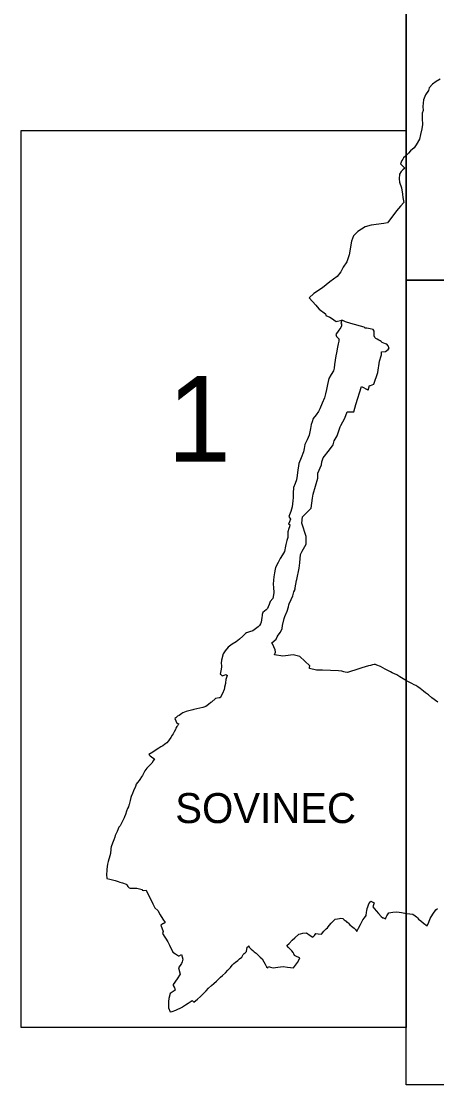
# Model space of a CAD drawing. Extents: x -547343 to -529607, y -1096298 to -1087453.
# Drawn here: x -535595.4 to -535501.3, y -1089568.3 to -1089327.3 of the extents above; entities that cross this region are included whole.
import ezdxf

# ---------------------------------------------------------------- set-up
doc = ezdxf.new("R2010")
doc.units = 0
doc.layers.add('Vrstva 18', color=7, linetype='Continuous')
doc.layers.add('Vrstva 9', color=7, linetype='Continuous')

msp = doc.modelspace()

# ---------------------------------------------------------------- linework, layer by layer
at = {"layer": 'Vrstva 18'}
for points in [[(-535421.05, -1089203.69), (-535508.22, -1089203.69), (-535508.22, -1089386.02), (-535421.05, -1089386.02)], [(-535508.22, -1089352.1), (-535508.22, -1089555.37), (-535595.39, -1089555.37), (-535595.39, -1089352.1)], [(-535421.05, -1089386.02), (-535421.05, -1089568.34), (-535508.22, -1089568.34), (-535508.22, -1089386.02)]]:
    msp.add_lwpolyline(points, close=True, dxfattribs=at)
for points in [[(-535500.53, -1089340.43), (-535501.42, -1089340.96), (-535502.32, -1089341.55), (-535503.04, -1089342.41), (-535503.2, -1089343.02), (-535503.9, -1089344.01), (-535504.36, -1089345.11), (-535504.45, -1089346.64), (-535504.37, -1089347.55), (-535504.59, -1089348.18), (-535504.66, -1089349.38), (-535504.57, -1089350.69), (-535504.67, -1089351.72), (-535504.99, -1089352.99), (-535505.24, -1089354.03), (-535505.98, -1089355.32), (-535506.47, -1089356), (-535507.27, -1089356.66), (-535507.75, -1089357.22), (-535508.42, -1089357.88), (-535508.82, -1089358.3), (-535508.98, -1089358.61), (-535509.25, -1089358.88), (-535509.51, -1089359.62), (-535509.17, -1089360.03), (-535508.53, -1089360.59), (-535508.97, -1089361.01), (-535509.37, -1089361.39), (-535509.77, -1089361.95), (-535509.84, -1089363.02), (-535509.77, -1089363.78), (-535509.33, -1089365.09), (-535509.09, -1089366.52), (-535509, -1089367.28), (-535508.78, -1089368.41), (-535509.53, -1089369.24), (-535510.45, -1089370.32), (-535511.07, -1089371.09), (-535512.27, -1089372.72), (-535512.45, -1089373), (-535513.34, -1089373.2), (-535516.16, -1089373.56), (-535517.56, -1089373.9), (-535519.23, -1089374.98), (-535520.16, -1089375.96), (-535520.62, -1089377.17), (-535521.15, -1089380.26), (-535521.65, -1089381.83), (-535522.55, -1089383.08), (-535523.01, -1089384.11), (-535523.86, -1089385.16), (-535525.57, -1089386.4), (-535527.22, -1089387.73), (-535529.16, -1089389.06), (-535530.23, -1089390.03), (-535528.72, -1089391.66), (-535528.41, -1089392.07), (-535527.96, -1089392.55), (-535526.54, -1089393.64), (-535526.43, -1089393.98), (-535525.53, -1089394.36), (-535524.94, -1089394.75), (-535524.6, -1089395), (-535524.1, -1089395.35), (-535522.78, -1089395.07), (-535523.03, -1089395.8), (-535522.86, -1089395.83), (-535522.89, -1089396.32), (-535523.08, -1089396.74), (-535523.48, -1089397.33), (-535524.17, -1089398.31), (-535523.99, -1089398.8), (-535523.45, -1089399.38), (-535523.49, -1089399.56), (-535523.53, -1089399.8), (-535523.66, -1089400.43), (-535523.79, -1089401.2), (-535524.02, -1089402.47), (-535524.15, -1089403.19), (-535524.32, -1089404.12), (-535524.46, -1089405.1), (-535524.58, -1089405.96), (-535524.67, -1089406.56), (-535525.21, -1089407.42), (-535525.73, -1089408.28), (-535526.05, -1089409.68), (-535526.3, -1089410.8), (-535526.54, -1089411.74), (-535526.77, -1089412.64), (-535527.29, -1089413.91), (-535527.8, -1089415.14), (-535528.07, -1089415.78), (-535528.63, -1089416.49), (-535529.34, -1089417.37), (-535529.55, -1089418.09), (-535529.74, -1089418.7), (-535529.9, -1089419.6), (-535530.06, -1089420.4), (-535530.18, -1089421.1), (-535530.66, -1089422.16), (-535531.17, -1089423.27), (-535531.32, -1089424.12), (-535531.48, -1089424.88), (-535532.02, -1089426.26), (-535532.55, -1089427.55), (-535532.82, -1089429.6), (-535532.93, -1089430.3), (-535533.06, -1089431.28), (-535533.39, -1089432.07), (-535533.78, -1089432.98), (-535533.84, -1089434.3), (-535533.86, -1089435.23), (-535533.9, -1089435.98), (-535533.96, -1089436.68), (-535534.03, -1089437.37), (-535534.4, -1089438.45), (-535534.78, -1089439.53), (-535534.45, -1089440.16), (-535534.69, -1089440.78), (-535534.91, -1089441.32), (-535534.61, -1089441.36), (-535534.64, -1089441.89), (-535534.78, -1089442.29), (-535535.03, -1089443.07), (-535535.05, -1089443.59), (-535535.08, -1089444.3), (-535535.25, -1089444.97), (-535535.5, -1089445.89), (-535535.58, -1089446.27), (-535535.81, -1089447.51), (-535536.28, -1089448.26), (-535536.8, -1089449.09), (-535537.25, -1089450), (-535537.8, -1089451.15), (-535537.88, -1089451.49), (-535538.08, -1089452.32), (-535538.24, -1089453.24), (-535538.3, -1089453.99), (-535538.36, -1089454.9), (-535538.3, -1089455.65), (-535538.22, -1089456.79), (-535538.3, -1089457.33), (-535538.41, -1089458.12), (-535539.05, -1089458.84), (-535539.27, -1089459.53), (-535539.47, -1089460.07), (-535539.61, -1089460.39), (-535539.96, -1089460.7), (-535540.7, -1089461.3), (-535540.85, -1089461.76), (-535540.86, -1089461.97), (-535540.9, -1089462.45), (-535541.06, -1089463.49), (-535541.25, -1089463.88), (-535541.49, -1089464.23), (-535541.78, -1089464.59), (-535542.33, -1089465.02), (-535542.97, -1089465.51), (-535543.69, -1089465.67), (-535544.37, -1089465.93), (-535544.59, -1089466.06), (-535545.25, -1089466.66), (-535546.01, -1089467.39), (-535546.76, -1089467.94), (-535547.62, -1089468.51), (-535548.57, -1089469.16), (-535549.22, -1089469.98), (-535549.55, -1089470.44), (-535549.68, -1089470.71), (-535550.04, -1089472.13), (-535550.1, -1089472.79), (-535550.03, -1089473.41), (-535550.08, -1089473.74), (-535550.24, -1089474.53), (-535550.34, -1089475.3), (-535550.24, -1089475.37), (-535549.95, -1089475.58), (-535549.95, -1089475.58), (-535549.93, -1089475.59), (-535549.85, -1089475.65), (-535549.06, -1089475.38), (-535548.98, -1089475.43), (-535548.86, -1089475.51), (-535548.79, -1089475.55), (-535548.77, -1089475.57), (-535549.09, -1089476.47), (-535549.15, -1089477.22), (-535549.17, -1089477.42), (-535549.35, -1089478.21), (-535549.38, -1089478.36), (-535549.48, -1089478.78), (-535549.8, -1089479.66), (-535550.4, -1089480.68), (-535550.5, -1089480.64), (-535550.62, -1089480.62), (-535551.42, -1089480.79), (-535552.35, -1089481.61), (-535552.46, -1089481.7), (-535553.04, -1089482.18), (-535553.61, -1089482.59), (-535554.31, -1089482.86), (-535556.33, -1089483.31), (-535556.55, -1089483.36), (-535556.83, -1089483.43), (-535558.09, -1089483.74), (-535558.46, -1089483.9), (-535558.82, -1089484.06), (-535559.08, -1089484.24), (-535559.67, -1089484.64), (-535559.99, -1089484.84), (-535560.39, -1089485.18), (-535560.62, -1089485.37), (-535560.42, -1089485.87), (-535560.15, -1089486.41), (-535559.75, -1089486.55), (-535559.85, -1089486.72), (-535560.03, -1089486.99), (-535560.15, -1089487.18), (-535560.39, -1089487.55), (-535560.51, -1089487.81), (-535560.79, -1089488.36), (-535560.99, -1089488.78), (-535561.22, -1089489.12), (-535561.54, -1089489.62), (-535561.9, -1089490.19), (-535562.07, -1089490.38), (-535562.46, -1089490.84), (-535562.65, -1089491.03), (-535562.97, -1089491.25), (-535563.38, -1089491.53), (-535563.77, -1089491.77), (-535564.24, -1089492.09), (-535564.83, -1089492.47), (-535565.62, -1089492.97), (-535566.5, -1089493.51), (-535566.42, -1089493.59), (-535566.21, -1089493.78), (-535565.64, -1089494.25), (-535565.21, -1089494.46), (-535565.5, -1089494.91), (-535565.85, -1089495.45), (-535566.21, -1089495.82), (-535566.62, -1089496.23), (-535566.98, -1089496.59), (-535567.18, -1089496.89), (-535567.41, -1089497.2), (-535567.66, -1089497.69), (-535567.95, -1089498.22), (-535568.17, -1089498.59), (-535568.57, -1089499.2), (-535568.69, -1089499.36), (-535569.1, -1089499.87), (-535569.35, -1089500.2), (-535569.57, -1089500.78), (-535569.95, -1089501.73), (-535570.2, -1089502.31), (-535570.5, -1089503), (-535570.57, -1089503.27), (-535570.73, -1089503.94), (-535570.96, -1089504.84), (-535571.02, -1089504.99), (-535571.15, -1089505.33), (-535571.33, -1089505.74), (-535571.55, -1089506.33), (-535571.81, -1089507.1), (-535572.01, -1089507.66), (-535572.11, -1089507.88), (-535572.7, -1089509.03), (-535573.04, -1089509.65), (-535573.27, -1089509.98), (-535573.44, -1089510.38), (-535573.72, -1089510.98), (-535574.13, -1089511.89), (-535574.24, -1089512.21), (-535574.46, -1089512.82), (-535574.75, -1089513.6), (-535575.05, -1089514.4), (-535575.11, -1089514.8), (-535575.13, -1089515.08), (-535575.19, -1089515.75), (-535575.23, -1089515.96), (-535575.37, -1089516.5), (-535575.71, -1089517.73), (-535575.88, -1089518.35), (-535575.92, -1089518.89), (-535575.99, -1089519.55), (-535576.02, -1089519.82), (-535576.1, -1089520.72), (-535576.01, -1089521.62), (-535575.38, -1089521.74), (-535574.71, -1089521.89), (-535574.16, -1089522.08), (-535573.45, -1089522.3), (-535573.05, -1089522.43), (-535572.46, -1089522.61), (-535571.62, -1089522.86), (-535571.46, -1089523.07), (-535571.24, -1089523.38), (-535570.99, -1089523.73), (-535570.77, -1089523.76), (-535570.19, -1089523.82), (-535569.24, -1089523.81), (-535568.29, -1089524.01), (-535568.06, -1089524.12), (-535568, -1089524.26), (-535567.79, -1089524.33), (-535567.1, -1089524.23), (-535565.63, -1089527.36), (-535565.12, -1089528.22), (-535564.44, -1089528.83), (-535563.95, -1089529.81), (-535563.37, -1089530.85), (-535562.78, -1089531.54), (-535563.15, -1089531.76), (-535563.32, -1089531.87), (-535563.78, -1089532.15), (-535563.25, -1089533.63), (-535563.39, -1089534.1), (-535562.18, -1089535.95), (-535561.85, -1089536.69), (-535561.09, -1089538.31), (-535560.48, -1089538.67), (-535559.81, -1089539.13), (-535559.63, -1089539.09), (-535559.09, -1089538.82), (-535558.84, -1089539.87), (-535558.95, -1089540.51), (-535559.09, -1089540.9), (-535559.78, -1089541.88), (-535559.43, -1089543.26), (-535560.08, -1089544.3), (-535561.04, -1089545.59), (-535561.02, -1089545.86), (-535560.78, -1089546.19), (-535560.7, -1089546.32), (-535560.63, -1089546.65), (-535560.58, -1089546.89), (-535561.68, -1089547.65), (-535561.97, -1089548.81), (-535562.06, -1089549.49), (-535562.09, -1089549.73), (-535562.09, -1089550.93), (-535561.69, -1089551.79), (-535561.22, -1089551.76), (-535560.37, -1089551.45), (-535559, -1089550.76), (-535558.87, -1089550.68), (-535558.18, -1089550.26), (-535557.61, -1089549.88), (-535556.68, -1089549.25), (-535556.47, -1089549.49), (-535556.33, -1089549.65), (-535555.47, -1089548.98), (-535554.81, -1089548.31), (-535554.31, -1089547.81), (-535553.56, -1089547.04), (-535552.99, -1089546.48), (-535552.32, -1089545.82), (-535551.83, -1089545.4), (-535551.22, -1089544.86), (-535550.79, -1089544.48), (-535550.26, -1089543.98), (-535549.81, -1089543.55), (-535549.19, -1089542.94), (-535548.64, -1089542.41), (-535548.01, -1089541.77), (-535547.61, -1089541.26), (-535547.28, -1089540.83), (-535546.87, -1089540.54), (-535546.38, -1089540.18), (-535545.97, -1089539.83), (-535545.48, -1089539.4), (-535545.3, -1089539.13), (-535545.12, -1089538.8), (-535544.92, -1089538.63), (-535544.74, -1089538.45), (-535544.43, -1089538.14), (-535544.26, -1089537.19), (-535544.05, -1089537.02), (-535543.87, -1089536.87), (-535543.82, -1089537.18), (-535543.48, -1089537.48), (-535543.33, -1089537.62), (-535542.98, -1089537.93), (-535542.64, -1089538.22), (-535542.24, -1089538.55), (-535541.91, -1089538.83), (-535541.62, -1089539.09), (-535541.28, -1089539.39), (-535540.82, -1089539.82), (-535540.48, -1089540.45), (-535540.19, -1089540.98), (-535539.86, -1089541.65), (-535539.56, -1089541.82), (-535539.41, -1089541.52), (-535538.93, -1089541.68), (-535538.37, -1089541.87), (-535537.31, -1089541.72), (-535536.12, -1089541.56), (-535535.12, -1089541.66), (-535533.73, -1089541.81), (-535533.33, -1089541.27), (-535532.84, -1089540.62), (-535532.56, -1089540.07), (-535532.35, -1089539.61), (-535532.9, -1089539.36), (-535533.56, -1089539.05), (-535533.69, -1089538.68), (-535533.81, -1089538.34), (-535534.14, -1089538.02), (-535534.88, -1089537.24), (-535535.3, -1089536.82), (-535534.77, -1089536.32), (-535534.03, -1089535.6), (-535533.45, -1089535.05), (-535532.54, -1089534.19), (-535532.19, -1089534.11), (-535531.63, -1089534.01), (-535530.85, -1089533.89), (-535529.98, -1089534.48), (-535529.37, -1089534.9), (-535529.04, -1089534.5), (-535528.67, -1089534.08), (-535528.15, -1089534.13), (-535527.42, -1089534.19), (-535526.86, -1089533.54), (-535526.38, -1089533), (-535526.08, -1089532.76), (-535525.67, -1089532.24), (-535525.24, -1089531.7), (-535524.8, -1089531.26), (-535524.33, -1089530.82), (-535523.8, -1089530.72), (-535523.38, -1089530.65), (-535523.07, -1089530.62), (-535522.6, -1089530.67), (-535522.26, -1089530.96), (-535521.87, -1089531.3), (-535521.68, -1089531.48), (-535521.57, -1089531.56), (-535521.4, -1089531.64), (-535521.02, -1089532.1), (-535520.61, -1089532.41), (-535520.04, -1089532.82), (-535519.75, -1089533.18), (-535519.4, -1089533.59), (-535519.03, -1089532.88), (-535518.61, -1089532.04), (-535518.35, -1089531.55), (-535518.04, -1089530.95), (-535517.69, -1089530.48), (-535517.34, -1089530), (-535517.2, -1089529.23), (-535517.14, -1089528.89), (-535517.05, -1089528.43), (-535516.93, -1089528.01), (-535516.73, -1089527.34), (-535516.28, -1089526.74), (-535515.47, -1089527.15), (-535515.79, -1089528.01), (-535515.05, -1089528.96), (-535514.48, -1089529.56), (-535513.89, -1089530.19), (-535513.51, -1089530.49), (-535513.4, -1089530.55), (-535512.9, -1089530.75), (-535512.75, -1089530.35), (-535512.62, -1089530.08), (-535512.2, -1089529.38), (-535511.28, -1089529.25), (-535510.35, -1089529.13), (-535509.29, -1089529.32), (-535508.17, -1089529.5), (-535507.45, -1089529.62), (-535506.72, -1089529.72), (-535506.2, -1089530.07), (-535505.91, -1089530.26), (-535505.69, -1089530.53), (-535505.42, -1089530.84), (-535504.9, -1089531.23), (-535504.32, -1089531.69), (-535503.46, -1089532.35), (-535503.09, -1089531.46), (-535502.8, -1089530.69), (-535502.21, -1089529.7), (-535501.54, -1089528.68), (-535501.17, -1089528.39)], [(-535513.86, -1089402.92), (-535513.81, -1089402.46), (-535513.8, -1089402.27), (-535512.94, -1089402.16), (-535512.36, -1089401.71), (-535512.18, -1089401.52), (-535512.12, -1089401.46), (-535512.36, -1089400.88), (-535512.63, -1089400.54), (-535512.91, -1089400.44), (-535513.27, -1089400.31), (-535513.72, -1089400.1), (-535513.91, -1089399.93), (-535514.14, -1089399.72), (-535514.47, -1089399.59), (-535514.83, -1089399.41), (-535515.13, -1089399.22), (-535515.32, -1089398.99), (-535515.45, -1089398.78), (-535515.5, -1089398.7), (-535515.51, -1089398.49), (-535515.5, -1089398.34), (-535515.49, -1089397.98), (-535515.47, -1089397.6), (-535515.72, -1089397.17), (-535516.4, -1089397.05), (-535517.17, -1089396.92), (-535517.56, -1089396.88), (-535517.59, -1089396.83), (-535517.73, -1089396.69), (-535520.77, -1089395.79), (-535521.96, -1089395.43), (-535522.47, -1089395.21), (-535522.62, -1089395.14), (-535522.78, -1089395.07)], [(-535501.1, -1089481.67), (-535502.45, -1089480.66), (-535503.18, -1089479.97), (-535503.85, -1089479.52), (-535504.33, -1089479.15), (-535505.1, -1089478.53), (-535505.62, -1089478.16), (-535506.03, -1089477.89), (-535506.42, -1089477.7), (-535506.94, -1089477.43), (-535508.19, -1089476.8), (-535508.55, -1089476.57), (-535509.65, -1089475.9), (-535510.13, -1089475.59), (-535510.36, -1089475.48), (-535510.86, -1089475.25), (-535511.45, -1089474.98), (-535511.83, -1089474.79), (-535512.28, -1089474.53), (-535512.98, -1089474.13), (-535514.06, -1089473.53), (-535514.86, -1089473.26), (-535515.23, -1089473.14), (-535515.35, -1089473.12), (-535515.49, -1089473.14), (-535515.88, -1089473.2), (-535516.31, -1089473.3), (-535516.81, -1089473.44), (-535518.3, -1089473.88), (-535519.89, -1089474.36), (-535520.65, -1089474.6), (-535521.51, -1089474.88), (-535522.05, -1089474.83), (-535522.38, -1089474.73), (-535522.79, -1089474.6), (-535523.57, -1089474.57), (-535525.37, -1089474.49), (-535527.2, -1089474.41), (-535528.55, -1089474.35), (-535530.11, -1089473.99), (-535530.11, -1089473.93), (-535530.1, -1089473.78), (-535530.07, -1089473.37), (-535532.35, -1089471.32), (-535533.81, -1089470.94), (-535535.56, -1089471.15), (-535536.19, -1089471.22), (-535538.06, -1089470.91), (-535537.98, -1089470.7), (-535537.91, -1089470.52), (-535537.81, -1089470.31), (-535537.91, -1089469.81), (-535538.49, -1089468.44), (-535538.63, -1089468.24), (-535538.66, -1089468.19), (-535537.67, -1089467.34), (-535537.43, -1089466.84), (-535537.26, -1089466.48), (-535536.69, -1089465.74), (-535536.36, -1089464.97), (-535536.22, -1089464.3), (-535535.89, -1089462.69), (-535535.69, -1089462.21), (-535535.19, -1089461.03), (-535534.87, -1089460.01), (-535534.79, -1089459.6), (-535534.71, -1089459.34), (-535534.29, -1089458.36), (-535533.93, -1089457.55), (-535533.84, -1089457.23), (-535533.7, -1089456.63), (-535533.45, -1089456.26), (-535533.38, -1089456.01), (-535533.44, -1089456.01), (-535533.39, -1089455.8), (-535533.37, -1089455.7), (-535533.06, -1089454.1), (-535533.02, -1089453.86), (-535532.51, -1089451.24), (-535532.3, -1089450.08), (-535532.2, -1089448.16), (-535531.79, -1089447.43), (-535530.91, -1089445.84), (-535530.91, -1089444.1), (-535531.84, -1089441.07), (-535531.72, -1089439.63), (-535529.76, -1089437.68), (-535529.42, -1089435.42), (-535529.28, -1089434.47), (-535528.28, -1089430.89), (-535528.23, -1089429.77), (-535527.41, -1089427.85), (-535527.32, -1089427.14), (-535527.01, -1089426.29), (-535525.63, -1089424.43), (-535524.79, -1089423.29), (-535524.56, -1089422.43), (-535523.85, -1089421.25), (-535523.23, -1089419.28), (-535523.02, -1089418.93), (-535522.16, -1089417.31), (-535521.64, -1089415.81), (-535521.52, -1089415.82), (-535520.1, -1089415.81), (-535519.65, -1089414.16), (-535518.37, -1089410.07), (-535516.95, -1089410.84), (-535516.84, -1089410.9), (-535516.56, -1089409.91), (-535516.36, -1089409.85), (-535515.55, -1089409.58), (-535514.67, -1089406.91), (-535514.26, -1089404.37), (-535513.88, -1089403.19), (-535513.86, -1089402.92)]]:
    msp.add_lwpolyline(points, dxfattribs=at)
at = {"layer": 'Vrstva 9'}
for points in [[(-535508.22, -1089203.69), (-535421.05, -1089203.69), (-535421.05, -1089386.02), (-535508.22, -1089386.02)], [(-535595.39, -1089352.1), (-535508.22, -1089352.1), (-535508.22, -1089555.37), (-535595.39, -1089555.37)], [(-535508.22, -1089386.02), (-535421.05, -1089386.02), (-535421.05, -1089568.34), (-535508.22, -1089568.34)]]:
    msp.add_lwpolyline(points, close=True, dxfattribs=at)

# ---------------------------------------------------------------- texts
at = {"layer": 'Vrstva 18'}
for s, height, p in [('1', 19.37, (-535562.31, -1089427.13)), ('SOVINEC', 6.799, (-535560.53, -1089509.04))]:
    msp.add_text(s, height=height, dxfattribs=at).set_placement(p)

doc.saveas('drawing.dxf')
